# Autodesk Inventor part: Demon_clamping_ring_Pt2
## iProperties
Shininess: 64.0
Length Units: 11269
Angle Units: 11279
Time Units: 11290
Mass Units: 11283
Length Display Precision: 3
Angle Display Precision: 2
Compacted: True
Part Number: Demon_clamping_ring_Pt2
Document SubType Name: Modeling
Created: 2005-04
Designer: John Blackburn
Manufacturer: Standard
Standards Organization: Custom
Density: 0.0
Volumn: 0.0
Area: 0.0
PropertySet Name: Model Information
Control State: 0
Master: False
Checked Out: False
Author: John Blackburn
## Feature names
1. Extrusion1
2. Extrusion2
